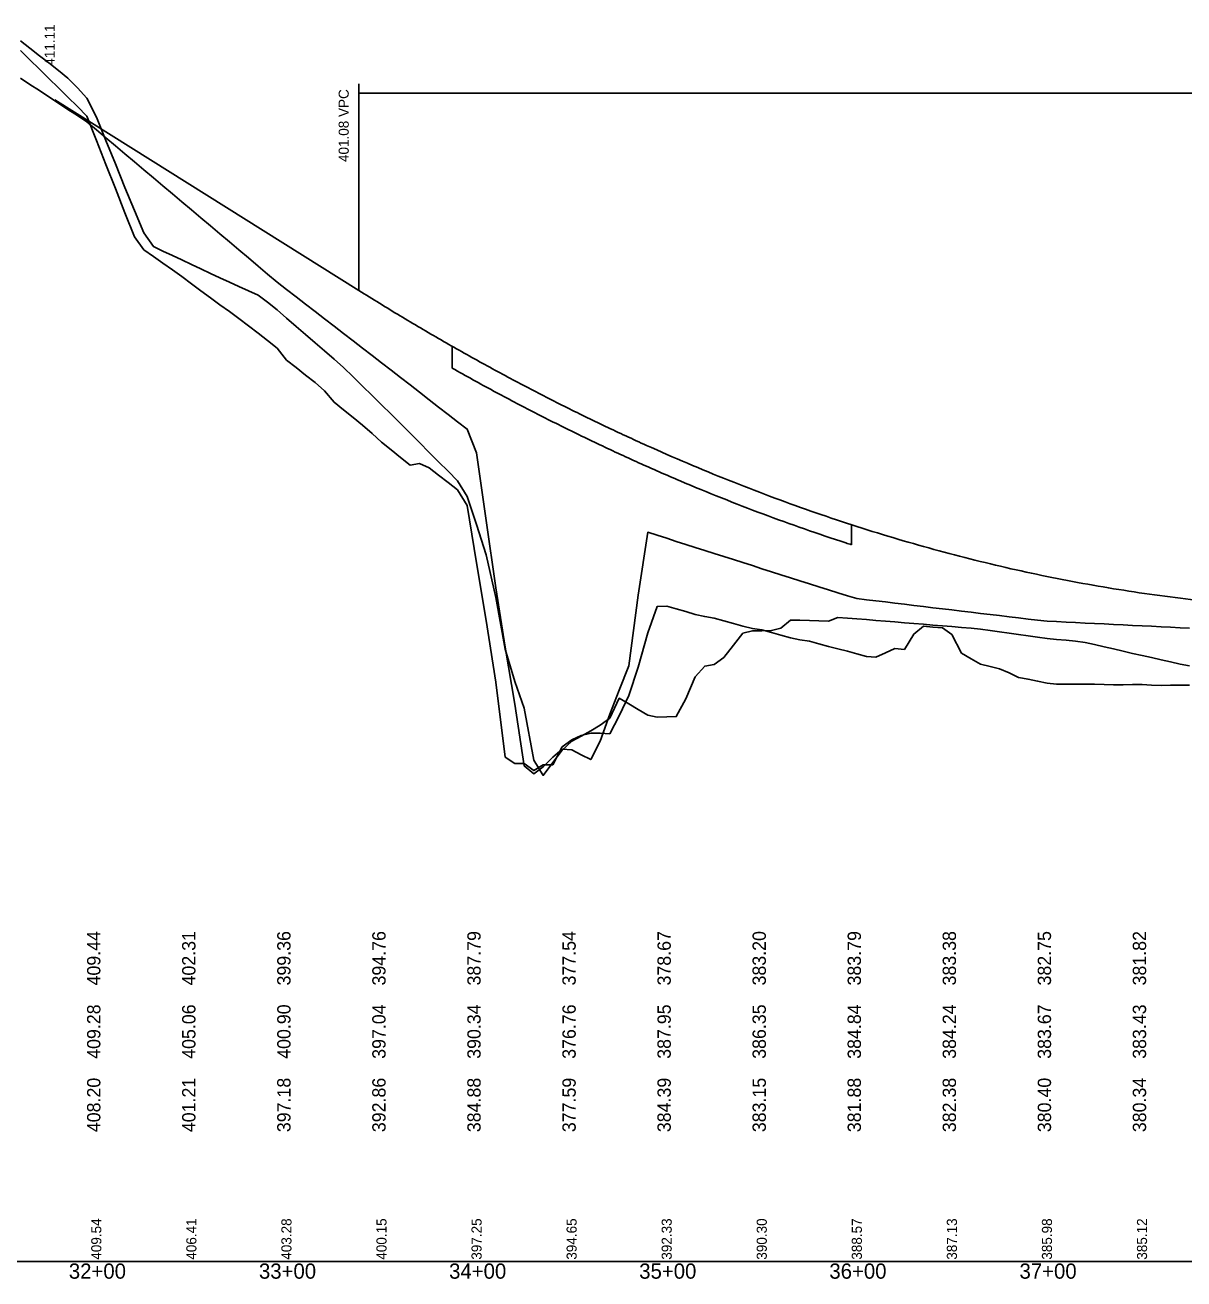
# Model space of a CAD drawing. Extents: x 2116146 to 2121546, y 979095 to 984095.
# Drawn here: x 2118529 to 2119138, y 981586 to 982246 of the extents above; entities that cross this region are included whole.
import ezdxf

# ---------------------------------------------------------------- set-up
doc = ezdxf.new("R2010")
doc.units = 0
for name, color, linetype in [('RD_DDB_Profile_EX', 7, 'Continuous'), ('RD_DDB_Profile_Lbl', 7, 'Continuous'), ('RD_DDB_Profile_PR', 7, 'Continuous'), ('RD_DDB_StaTX', 7, 'Continuous'), ('RD_DDB_StripGrade', 7, 'Continuous'), ('RD_DDB_VCLbl', 7, 'Continuous'), ('RD_GPK_Profile_Cell', 7, 'Continuous'), ('RD_PD_Bridge', 7, 'Continuous'), ('RD_Sketch2', 7, 'Continuous')]:
    doc.layers.add(name, color=color, linetype=linetype)

msp = doc.modelspace()

# ---------------------------------------------------------------- linework, layer by layer
at = {"layer": 'RD_DDB_Profile_EX'}
for points in [[(2118526.02, 982218.06), (2118531.02, 982214.77), (2118536.02, 982211.48), (2118541.02, 982208.19), (2118546.02, 982204.91), (2118551.02, 982201.62), (2118556.02, 982198.33), (2118561.02, 982195.04), (2118566.02, 982190.88), (2118571.02, 982186.67), (2118576.02, 982182.46), (2118581.02, 982178.25), (2118586.02, 982174.04), (2118591.02, 982169.82), (2118596.02, 982165.61), (2118601.02, 982161.39), (2118606.02, 982157.18), (2118611.02, 982152.96), (2118616.02, 982148.74), (2118621.02, 982144.53), (2118626.02, 982140.31), (2118631.02, 982136.1), (2118636.02, 982131.88), (2118641.02, 982127.65), (2118646.02, 982123.44), (2118651.02, 982119.22), (2118656.02, 982115), (2118661.02, 982110.79), (2118666.02, 982106.9), (2118671.02, 982103.04), (2118676.02, 982099.19), (2118681.02, 982095.34), (2118686.02, 982091.49), (2118691.02, 982087.63), (2118696.02, 982083.78), (2118701.02, 982079.93), (2118706.02, 982076.05), (2118711.02, 982072.17), (2118716.02, 982068.3), (2118721.02, 982064.42), (2118726.02, 982060.54), (2118731.02, 982056.66), (2118736.02, 982052.78), (2118741.02, 982048.9), (2118746.02, 982045.03), (2118751.02, 982041.15), (2118756.02, 982037.27)], [(2118756.02, 982037.27), (2118761.02, 982033.39), (2118766.02, 982020.86), (2118771.02, 981985.39), (2118776.02, 981949.93), (2118781.02, 981918.69), (2118786.02, 981888.78), (2118791.02, 981856.27), (2118796.02, 981852.15), (2118801.02, 981855.83), (2118806.02, 981860.84), (2118811.02, 981865), (2118816.02, 981864.63), (2118821.02, 981862.11), (2118826.02, 981859.59), (2118831.02, 981869.26), (2118836.02, 981883.5), (2118841.02, 981896.17), (2118846.02, 981908.84), (2118851.02, 981945.98), (2118856.02, 981979.14), (2118861.02, 981977.55), (2118866.02, 981975.96), (2118871.02, 981974.37), (2118876.02, 981972.78), (2118881.02, 981971.15), (2118886.02, 981969.56), (2118891.02, 981967.97), (2118896.02, 981966.38), (2118901.02, 981964.79), (2118906.02, 981963.16), (2118911.02, 981961.58), (2118916.02, 981959.99), (2118921.02, 981958.4), (2118926.02, 981956.81), (2118931.02, 981955.19), (2118936.02, 981953.61), (2118941.02, 981952.02), (2118946.02, 981950.43), (2118951.02, 981948.84), (2118956.02, 981947.24), (2118961.02, 981945.65), (2118966.02, 981944.3), (2118971.02, 981943.69), (2118976.02, 981943.08), (2118981.02, 981942.48), (2118986.02, 981941.87), (2118991.02, 981941.29), (2118996.02, 981940.68), (2119001.02, 981940.07), (2119006.02, 981939.46), (2119011.02, 981938.85), (2119016.02, 981938.26), (2119021.02, 981937.65), (2119026.02, 981937.04), (2119031.02, 981936.44), (2119036.02, 981935.83), (2119041.02, 981935.28), (2119046.02, 981934.67), (2119051.02, 981934.06), (2119056.02, 981933.45), (2119061.02, 981932.85), (2119066.02, 981932.37), (2119071.02, 981932.13), (2119076.02, 981931.88), (2119081.02, 981931.64), (2119086.02, 981931.39), (2119091.02, 981931.14), (2119096.02, 981930.9), (2119101.02, 981930.65), (2119106.02, 981930.41), (2119111.02, 981930.16), (2119116.02, 981929.92), (2119121.02, 981929.67), (2119126.02, 981929.43), (2119131.02, 981929.19), (2119136.02, 981928.95), (2119141.02, 981928.7)]]:
    msp.add_lwpolyline(points, dxfattribs=at)
at = {"layer": 'RD_DDB_Profile_PR'}
msp.add_line((2118544.12, 982206.58), (2118704.12, 982106.3), dxfattribs=at)
msp.add_spline([(2118704.12, 982106.3), (2118725.72, 982093.03), (2118747.32, 982080.31), (2118768.92, 982068.13), (2118790.52, 982056.5), (2118812.12, 982045.41), (2118833.72, 982034.87), (2118855.32, 982024.87), (2118876.92, 982015.42), (2118898.52, 982006.51), (2118920.12, 981998.14), (2118941.72, 981990.32), (2118963.32, 981983.05), (2118984.92, 981976.32), (2119006.52, 981970.13), (2119028.12, 981964.49), (2119049.72, 981959.39), (2119071.32, 981954.84), (2119092.92, 981950.83), (2119114.52, 981947.37), (2119136.12, 981944.45), (2119157.72, 981942.07), (2119179.32, 981940.24), (2119200.92, 981938.96), (2119222.52, 981938.22), (2119244.12, 981938.02), (2119265.72, 981938.37), (2119287.32, 981939.26), (2119308.92, 981940.7), (2119330.52, 981942.68), (2119352.12, 981945.21), (2119373.72, 981948.28), (2119395.32, 981951.89), (2119416.92, 981956.05), (2119438.52, 981960.76), (2119460.12, 981966.01), (2119481.72, 981971.8), (2119503.32, 981978.14), (2119524.92, 981985.03), (2119546.52, 981992.45), (2119568.12, 982000.43), (2119589.72, 982008.94), (2119611.32, 982018), (2119632.92, 982027.61), (2119654.52, 982037.76), (2119676.12, 982048.46), (2119697.72, 982059.7), (2119719.32, 982071.48), (2119740.92, 982083.81), (2119762.52, 982096.68), (2119784.12, 982110.1)], degree=3, dxfattribs=at)
at = {"layer": 'RD_DDB_VCLbl'}
for p, q in [((2118704.12, 982215.1), (2118704.12, 982106.3)), ((2118704.12, 982210.1), (2119784.12, 982210.1))]:
    msp.add_line(p, q, dxfattribs=at)
at = {"layer": 'RD_GPK_Profile_Cell'}
msp.add_line((2117569.12, 981595.48), (2119869.12, 981595.48), dxfattribs=at)
at = {"layer": 'RD_PD_Bridge'}
for p, q in [((2118753.12, 982065.49), (2118753.12, 982076.99)), ((2118963.12, 981972.6), (2118963.12, 981983.11))]:
    msp.add_line(p, q, dxfattribs=at)
msp.add_spline([(2118753.12, 982065.49), (2118764.09, 982059.38), (2118785.86, 982047.65), (2118807.64, 982036.47), (2118829.42, 982025.84), (2118851.21, 982015.75), (2118873.01, 982006.21), (2118894.81, 981997.22), (2118916.61, 981988.78), (2118938.42, 981980.88), (2118960.23, 981973.54), (2118963.12, 981972.6)], degree=3, dxfattribs=at)
at = {"layer": 'RD_Sketch2'}
for points in [[(2118526.02, 982237.69), (2118531.02, 982233.75), (2118536.02, 982229.81), (2118541.02, 982226.11), (2118546.02, 982222.08), (2118551.02, 982218.02), (2118556.02, 982212.88), (2118561.02, 982207.46), (2118566.02, 982197.56), (2118571.02, 982185.23), (2118576.02, 982172.91), (2118581.02, 982160.58), (2118586.02, 982148.35), (2118591.02, 982136.73), (2118596.02, 982129.5), (2118601.02, 982127.08), (2118606.02, 982124.73), (2118611.02, 982122.4), (2118616.02, 982120.02), (2118621.02, 982117.67), (2118626.02, 982115.36), (2118631.02, 982113.05), (2118636.02, 982110.74), (2118641.02, 982108.42), (2118646.02, 982106.11), (2118651.02, 982103.81), (2118656.02, 982100.2), (2118661.02, 982096.1), (2118666.02, 982091.79), (2118671.02, 982087.47), (2118676.02, 982083.15), (2118681.02, 982078.83), (2118686.02, 982074.52), (2118691.02, 982070.2), (2118696.02, 982065.87), (2118701.02, 982060.98), (2118706.02, 982056.09), (2118711.02, 982051.15), (2118716.02, 982046.14), (2118721.02, 982041.21), (2118726.02, 982036.28), (2118731.02, 982031.35), (2118736.02, 982026.33), (2118741.02, 982021.17), (2118746.02, 982016.21), (2118751.02, 982011.24), (2118756.02, 982006.27)], [(2118526.02, 982232.55), (2118531.02, 982227.65), (2118536.02, 982222.75), (2118541.02, 982217.85), (2118546.02, 982212.95), (2118551.02, 982208.05), (2118556.02, 982203.15), (2118561.02, 982197.96), (2118566.02, 982185.31), (2118571.02, 982172.66), (2118576.02, 982159.97), (2118581.02, 982147.19), (2118586.02, 982134.54), (2118591.02, 982127.8), (2118596.02, 982124.29), (2118601.02, 982120.78), (2118606.02, 982117.26), (2118611.02, 982113.67), (2118616.02, 982109.89), (2118621.02, 982106.1), (2118626.02, 982102.43), (2118631.02, 982098.82), (2118636.02, 982095.2), (2118641.02, 982091.53), (2118646.02, 982087.7), (2118651.02, 982083.86), (2118656.02, 982080.03), (2118661.02, 982075.91), (2118666.02, 982069.69), (2118671.02, 982065.76), (2118676.02, 982061.84), (2118681.02, 982057.92), (2118686.02, 982053.63), (2118691.02, 982047.55), (2118696.02, 982043.55), (2118701.02, 982039.56), (2118706.02, 982035.57), (2118711.02, 982031.14), (2118716.02, 982026.57), (2118721.02, 982022.55), (2118726.02, 982018.53), (2118731.02, 982014.51), (2118736.02, 982015.26), (2118741.02, 982013.06), (2118746.02, 982009.19), (2118751.02, 982005.31), (2118756.02, 982001.44)], [(2118756.02, 982006.27), (2118761.02, 981997.91), (2118766.02, 981983.3), (2118771.02, 981967.27), (2118776.02, 981944.85), (2118781.02, 981917.69), (2118786.02, 981900.69), (2118791.02, 981886.66), (2118796.02, 981859.18), (2118801.02, 981851.27), (2118806.02, 981858.04), (2118811.02, 981864.56), (2118816.02, 981869.17), (2118821.02, 981871.93), (2118826.02, 981874.69), (2118831.02, 981877.76), (2118836.02, 981881.4), (2118841.02, 981891.79), (2118846.02, 981888.86), (2118851.02, 981885.93), (2118856.02, 981882.99), (2118861.02, 981881.89), (2118866.02, 981882.05), (2118871.02, 981882.22), (2118876.02, 981891.6), (2118881.02, 981903.15), (2118886.02, 981908.74), (2118891.02, 981909.54), (2118896.02, 981913.25), (2118901.02, 981919.69), (2118906.02, 981926.14), (2118911.02, 981927.26), (2118916.02, 981927.37), (2118921.02, 981927.49), (2118926.02, 981928.64), (2118931.02, 981932.93), (2118936.02, 981932.88), (2118941.02, 981932.69), (2118946.02, 981932.5), (2118951.02, 981932.31), (2118956.02, 981934.28), (2118961.02, 981933.92), (2118966.02, 981933.63), (2118971.02, 981933.22), (2118976.02, 981932.82), (2118981.02, 981932.41), (2118986.02, 981932.01), (2118991.02, 981931.5), (2118996.02, 981931.11), (2119001.02, 981930.72), (2119006.02, 981930.32), (2119011.02, 981929.93), (2119016.02, 981929.5), (2119021.02, 981929.13), (2119026.02, 981928.75), (2119031.02, 981928.11), (2119036.02, 981927.43), (2119041.02, 981926.75), (2119046.02, 981926.06), (2119051.02, 981925.37), (2119056.02, 981924.69), (2119061.02, 981924), (2119066.02, 981923.27), (2119071.02, 981922.81), (2119076.02, 981922.34), (2119081.02, 981921.88), (2119086.02, 981921.19), (2119091.02, 981920.05), (2119096.02, 981918.9), (2119101.02, 981917.75), (2119106.02, 981916.6), (2119111.02, 981915.45), (2119116.02, 981914.37), (2119121.02, 981913.23), (2119126.02, 981912.1), (2119131.02, 981910.96), (2119136.02, 981909.85), (2119141.02, 981908.82)], [(2118756.02, 982001.44), (2118761.02, 981993.27), (2118766.02, 981963), (2118771.02, 981932.74), (2118776.02, 981900.34), (2118781.02, 981860.91), (2118786.02, 981857.58), (2118791.02, 981857.5), (2118796.02, 981853.8), (2118801.02, 981856.8), (2118806.02, 981856.79), (2118811.02, 981866.21), (2118816.02, 981870.01), (2118821.02, 981872.25), (2118826.02, 981873.45), (2118831.02, 981873.4), (2118836.02, 981873.18), (2118841.02, 981882.54), (2118846.02, 981893.26), (2118851.02, 981908.2), (2118856.02, 981926.2), (2118861.02, 981940.11), (2118866.02, 981940.26), (2118871.02, 981938.83), (2118876.02, 981937.4), (2118881.02, 981935.97), (2118886.02, 981934.78), (2118891.02, 981934), (2118896.02, 981932.59), (2118901.02, 981931.17), (2118906.02, 981929.76), (2118911.02, 981928.6), (2118916.02, 981927.89), (2118921.02, 981926.49), (2118926.02, 981925.08), (2118931.02, 981923.68), (2118936.02, 981922.56), (2118941.02, 981921.89), (2118946.02, 981920.53), (2118951.02, 981919.14), (2118956.02, 981917.75), (2118961.02, 981916.65), (2118966.02, 981915.23), (2118971.02, 981913.76), (2118976.02, 981913.4), (2118981.02, 981915.67), (2118986.02, 981917.93), (2118991.02, 981917.5), (2118996.02, 981925.56), (2119001.02, 981929.73), (2119006.02, 981929.18), (2119011.02, 981928.83), (2119016.02, 981925.32), (2119021.02, 981915.57), (2119026.02, 981912.51), (2119031.02, 981909.74), (2119036.02, 981908.55), (2119041.02, 981907.35), (2119046.02, 981905.16), (2119051.02, 981902.83), (2119056.02, 981901.83), (2119061.02, 981900.84), (2119066.02, 981899.84), (2119071.02, 981899.32), (2119076.02, 981899.2), (2119081.02, 981899.24), (2119086.02, 981899.28), (2119091.02, 981899.32), (2119096.02, 981899.03), (2119101.02, 981898.91), (2119106.02, 981898.95), (2119111.02, 981898.98), (2119116.02, 981899.02), (2119121.02, 981898.73), (2119126.02, 981898.62), (2119131.02, 981898.65), (2119136.02, 981898.68), (2119141.02, 981898.71)]]:
    msp.add_lwpolyline(points, dxfattribs=at)

# ---------------------------------------------------------------- texts
at = {"layer": 'RD_DDB_Profile_Lbl'}
msp.add_text('411.11', height=5.312, rotation=90, dxfattribs=at).set_placement((2118544.12, 982224.58))
at = {"layer": 'RD_DDB_StaTX'}
for s, p in [('32+00', (2118551.53, 981586.48)), ('33+00', (2118651.53, 981586.48)), ('34+00', (2118751.53, 981586.48)), ('35+00', (2118851.53, 981586.48)), ('36+00', (2118951.53, 981586.48)), ('37+00', (2119051.53, 981586.48))]:
    msp.add_text(s, height=8, dxfattribs=at).set_placement(p)
at = {"layer": 'RD_DDB_StripGrade'}
for s, height, p in [('401.08 VPC', 5.312, (2118698.74, 982173.92)), ('400.90', 7, (2118668.12, 981702.15)), ('397.04', 7, (2118718.12, 981702.15)), ('390.34', 7, (2118768.12, 981702.15)), ('384.84', 7, (2118968.12, 981702.15)), ('384.24', 7, (2119018.12, 981702.15)), ('409.28', 7, (2118568.12, 981702.15)), ('405.06', 7, (2118618.12, 981702.15)), ('376.76', 7, (2118818.12, 981702.15)), ('387.95', 7, (2118868.12, 981702.15)), ('386.35', 7, (2118918.12, 981702.15)), ('383.67', 7, (2119068.12, 981702.15)), ('383.43', 7, (2119118.12, 981702.15)), ('409.54', 5.312, (2118568.62, 981596.48)), ('406.41', 5.312, (2118618.62, 981596.48)), ('403.28', 5.312, (2118668.62, 981596.48)), ('400.15', 5.312, (2118718.62, 981596.48)), ('397.25', 5.312, (2118768.62, 981596.48)), ('394.65', 5.312, (2118818.62, 981596.48)), ('392.33', 5.312, (2118868.62, 981596.48)), ('390.30', 5.312, (2118918.62, 981596.48)), ('388.57', 5.312, (2118968.62, 981596.48)), ('387.13', 5.312, (2119018.62, 981596.48)), ('385.98', 5.312, (2119068.62, 981596.48)), ('385.12', 5.312, (2119118.62, 981596.48))]:
    msp.add_text(s, height=height, rotation=90, dxfattribs=at).set_placement(p)
at = {"layer": 'RD_Sketch2'}
for s, p in [('409.44', (2118568.12, 981740.73)), ('402.31', (2118618.12, 981740.73)), ('399.36', (2118668.12, 981740.73)), ('394.76', (2118718.12, 981740.73)), ('387.79', (2118768.12, 981740.73)), ('377.54', (2118818.12, 981740.73)), ('378.67', (2118868.12, 981740.73)), ('383.20', (2118918.12, 981740.73)), ('383.79', (2118968.12, 981740.73)), ('383.38', (2119018.12, 981740.73)), ('382.75', (2119068.12, 981740.73)), ('381.82', (2119118.12, 981740.73)), ('408.20', (2118568.12, 981663.56)), ('401.21', (2118618.12, 981663.56)), ('397.18', (2118668.12, 981663.56)), ('392.86', (2118718.12, 981663.56)), ('384.88', (2118768.12, 981663.56)), ('377.59', (2118818.12, 981663.56)), ('384.39', (2118868.12, 981663.56)), ('383.15', (2118918.12, 981663.56)), ('381.88', (2118968.12, 981663.56)), ('382.38', (2119018.12, 981663.56)), ('380.40', (2119068.12, 981663.56)), ('380.34', (2119118.12, 981663.56))]:
    msp.add_text(s, height=7, rotation=90, dxfattribs=at).set_placement(p)

doc.saveas('drawing.dxf')
